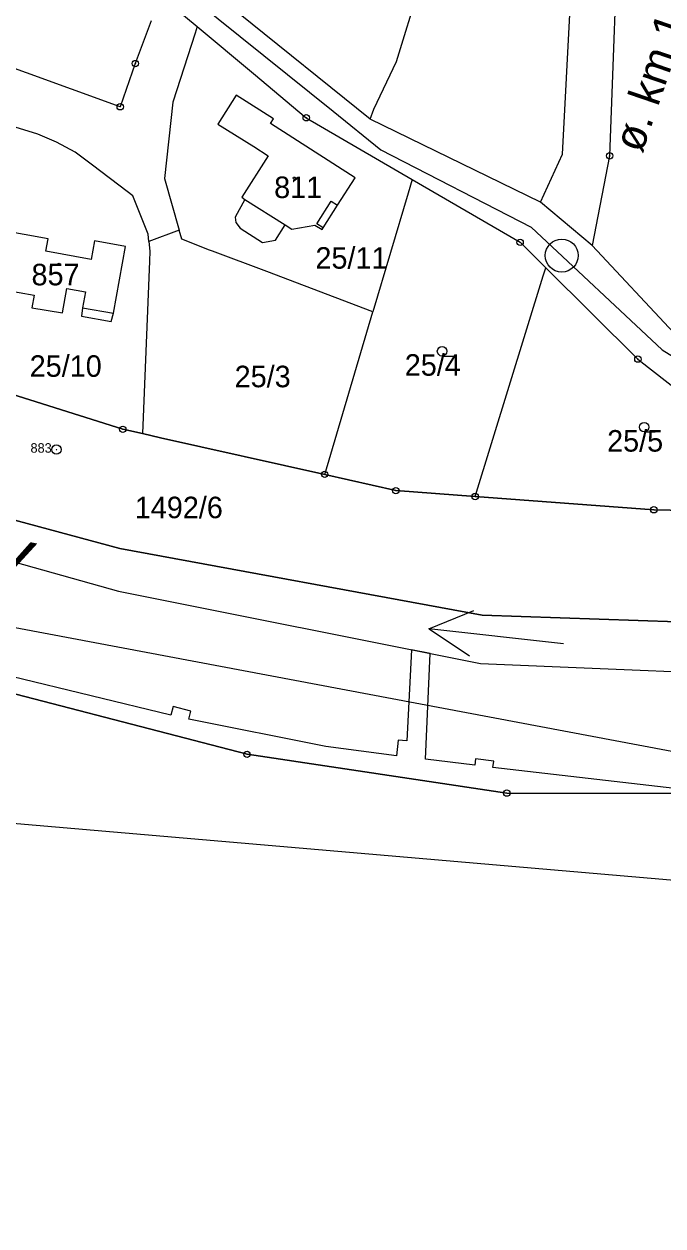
# Model space of a CAD drawing. Extents: x -537341 to -532984, y -1143469 to -1141314.
# Drawn here: x -533883.6 to -533782.7, y -1143459.1 to -1143269.2 of the extents above; entities that cross this region are included whole.
import ezdxf

# ---------------------------------------------------------------- set-up
doc = ezdxf.new("R2010")
doc.units = 0
for name, color, linetype in [('Hranice parcel', 7, 'Continuous'), ('parcelní_č_2000', 7, 'Continuous'), ('U_KM', 7, 'Continuous'), ('u_km_popis', 7, 'Continuous'), ('u_nadpis', 7, 'Continuous'), ('u_obec_Horní_Moš', 7, 'Continuous'), ('u_osa_stávající', 7, 'Continuous'), ('u_popis', 7, 'Continuous'), ('u_povodí', 7, 'Continuous'), ('Vnitřní kresba', 7, 'Continuous'), ('Věcná břemena k části', 7, 'Continuous'), ('x_formát_rám', 7, 'Continuous'), ('Značky bodu BP', 7, 'Continuous'), ('Značky budov', 7, 'Continuous'), ('Značky kultur', 7, 'Continuous')]:
    doc.layers.add(name, color=color, linetype=linetype)

# ---------------------------------------------------------------- blocks, each defined once
blk = doc.blocks.new('BIG')
at = {"layer": 'x_formát_rám'}
blk.add_line((0, 0), (-2100, 0), dxfattribs=at)

msp = doc.modelspace()

# ---------------------------------------------------------------- linework, layer by layer
at = {"layer": 'Hranice parcel'}
for p, q in [((-533862.31, -1143264.57), (-533856.28, -1143269.61)), ((-533828.95, -1143284.25), (-533849.76, -1143267.52)), ((-533802.08, -1143297.35), (-533828.95, -1143284.25)), ((-533793.92, -1143304.2), (-533802.08, -1143297.35)), ((-533859.12, -1143301.8), (-533863.9, -1143303.57)), ((-533781.01, -1143318), (-533793.92, -1143304.2)), ((-533836.14, -1143340.37), (-533828.52, -1143314.67))]:
    msp.add_line(p, q, dxfattribs=at)
for points in [[(-533785.04, -1143125.67), (-533791.14, -1143290.05), (-533793.92, -1143304.2)], [(-533828.95, -1143284.25), (-533828.36, -1143282.65), (-533824.78, -1143275.15), (-533821.19, -1143263.28), (-533817.82, -1143250.63), (-533816.72, -1143245.43), (-533815.35, -1143235.1), (-533814.52, -1143216.93), (-533815.7, -1143194.22), (-533815.75, -1143181.63), (-533815.27, -1143169.55)], [(-533802.08, -1143297.35), (-533798.61, -1143289.77), (-533794.82, -1143217.51), (-533793.35, -1143185), (-533793.03, -1143178.1), (-533793.07, -1143172.13)], [(-533863.56, -1143268.71), (-533866.06, -1143275.46), (-533868.45, -1143282.29), (-533905.8, -1143268.78)], [(-533856.28, -1143269.61), (-533856.63, -1143270.68), (-533860.15, -1143281.57), (-533861.44, -1143293.6), (-533859.12, -1143301.8)], [(-533856.28, -1143269.61), (-533847.4, -1143277.05), (-533839.06, -1143284.03), (-533822.32, -1143293.76)], [(-533853, -1143285.04), (-533847.34, -1143288.55), (-533845.07, -1143290.02), (-533849.26, -1143296.56), (-533848.74, -1143296.94), (-533850.31, -1143299.73), (-533850.18, -1143300.56), (-533849.48, -1143301.48), (-533845.96, -1143303.74), (-533843.91, -1143303.39), (-533842.37, -1143300.96), (-533841.35, -1143301.62), (-533837.69, -1143300.99), (-533836.55, -1143301.7), (-533836.38, -1143301.41), (-533834.1, -1143297.85), (-533831.35, -1143293.52), (-533844.73, -1143284.94), (-533844.22, -1143284.22), (-533850.14, -1143280.47), (-533853, -1143285.04)], [(-533863.9, -1143303.57), (-533864.01, -1143302.42), (-533866.44, -1143296.36), (-533867.33, -1143295.68), (-533872.81, -1143291.53), (-533875.55, -1143289.45), (-533878.53, -1143287.86), (-533881.44, -1143286.63), (-533887.8, -1143284.68)], [(-533822.32, -1143293.76), (-533822.97, -1143295.95), (-533828.52, -1143314.67)], [(-533822.32, -1143293.76), (-533805.28, -1143303.7), (-533801.24, -1143307.71)], [(-533635.65, -1143320.18), (-533621.98, -1143333.2), (-533669.13, -1143344.24), (-533673.43, -1143345.3), (-533684.54, -1143348.05), (-533705.36, -1143354.2), (-533711.3, -1143360.94), (-533727.16, -1143363.51), (-533755.86, -1143364.49), (-533811.29, -1143362.59), (-533868.5, -1143352.06), (-533907.21, -1143341.67), (-533958.4, -1143321.33), (-533977.94, -1143313.89), (-533996.94, -1143308.99), (-534032.19, -1143303.36), (-534039.92, -1143302.81)], [(-533882.39, -1143314.08), (-533877.55, -1143314.85), (-533876.87, -1143310.99), (-533873.95, -1143311.52), (-533874.41, -1143314.05), (-533874.56, -1143315.37), (-533869.86, -1143316.19), (-533869.51, -1143314.89), (-533867.62, -1143304.34), (-533872.5, -1143303.48), (-533873.01, -1143306.4), (-533880.19, -1143305.09), (-533879.84, -1143303.16), (-533887.46, -1143301.77), (-533889.21, -1143310.78), (-533882.03, -1143312.06), (-533882.39, -1143314.08)], [(-533828.52, -1143314.67), (-533845.29, -1143308.34), (-533853.85, -1143305.12), (-533854.32, -1143304.93), (-533858.73, -1143303.19), (-533859.12, -1143301.8)], [(-533863.9, -1143303.57), (-533863.77, -1143305.1), (-533863.83, -1143306.69), (-533864.93, -1143333.93)], [(-533812.37, -1143343.86), (-533801.63, -1143308.99), (-533801.24, -1143307.71)], [(-533801.24, -1143307.71), (-533786.68, -1143322.16), (-533777.13, -1143329.62), (-533764.51, -1143333.99)], [(-534038.97, -1143310.06), (-534031.18, -1143311.01), (-533998.92, -1143316.01), (-533979.87, -1143320.72), (-533960.35, -1143327.43), (-533909.08, -1143347.5), (-533868.71, -1143358.81), (-533811.53, -1143370.24), (-533756.11, -1143372.54), (-533679.67, -1143371.28), (-533668.56, -1143368.57), (-533664.28, -1143367.52), (-533654.7, -1143361.35), (-533580.69, -1143335.71), (-533556.9, -1143328.13)], [(-533895.36, -1143324.61), (-533889.64, -1143326.42), (-533868.04, -1143333.24), (-533864.93, -1143333.93)], [(-533864.93, -1143333.93), (-533862.1, -1143334.57), (-533836.14, -1143340.37)], [(-533836.14, -1143340.37), (-533824.92, -1143342.93), (-533812.37, -1143343.86)], [(-533812.37, -1143343.86), (-533784.16, -1143345.96), (-533765.98, -1143346.34)], [(-533755.18, -1143390.81), (-533807.39, -1143390.72), (-533848.41, -1143384.59), (-533897.59, -1143371.84), (-533928.82, -1143360.36), (-533960.85, -1143348.22)]]:
    msp.add_lwpolyline(points, dxfattribs=at)
at = {"layer": 'U_KM'}
msp.add_circle((-533798.71, -1143305.8), 2.6, dxfattribs=at)
at = {"layer": 'u_nadpis'}
msp.add_lwpolyline([(-535757.21, -1143234.5), (-535708.7, -1143186.18), (-535532.3, -1143063.53), (-535234.92, -1142978.15), (-534703.86, -1143121.98), (-534494.71, -1143163.58), (-534139.73, -1143316.61), (-533671.97, -1143404.67)], dxfattribs=at)
at = {"layer": 'u_obec_Horní_Moš'}
for p, q in [((-533862.31, -1143264.57), (-533856.28, -1143269.61)), ((-533828.95, -1143284.25), (-533849.76, -1143267.52)), ((-533802.08, -1143297.35), (-533828.95, -1143284.25)), ((-533793.92, -1143304.2), (-533802.08, -1143297.35)), ((-533781.01, -1143318), (-533793.92, -1143304.2))]:
    msp.add_line(p, q, dxfattribs=at)
for points in [[(-533856.28, -1143269.61), (-533847.4, -1143277.05), (-533839.06, -1143284.03), (-533822.32, -1143293.76)], [(-533822.32, -1143293.76), (-533805.28, -1143303.7), (-533801.24, -1143307.71)], [(-533801.24, -1143307.71), (-533786.68, -1143322.16), (-533777.13, -1143329.62), (-533764.51, -1143333.99)]]:
    msp.add_lwpolyline(points, dxfattribs=at)
at = {"layer": 'u_osa_stávající'}
msp.add_lwpolyline([(-534029.94, -1143093), (-534024.36, -1143095.75), (-534018.54, -1143098.11), (-534002.63, -1143106.06), (-533979.52, -1143113.76), (-533965.65, -1143121.26), (-533942.32, -1143139.25), (-533937.74, -1143147.06), (-533937.26, -1143155.21), (-533938.57, -1143165.94), (-533939.01, -1143180.16), (-533935.95, -1143193.33), (-533920.3, -1143207.37), (-533896.4, -1143226.73), (-533870.02, -1143249.8), (-533856.71, -1143265.33), (-533834.82, -1143282.99), (-533827.26, -1143289.09), (-533803.51, -1143301.3), (-533782.84, -1143320.67), (-533772.42, -1143327.12)], dxfattribs=at)
at = {"layer": 'u_popis'}
for p, q in [((-533819.72, -1143364.75), (-533812.6, -1143361.85)), ((-533798.45, -1143367.15), (-533819.72, -1143364.75)), ((-533819.66, -1143364.77), (-533813.28, -1143369.03))]:
    msp.add_line(p, q, dxfattribs=at)
at = {"layer": 'u_povodí'}
for p, q in [((-533868.5, -1143352.06), (-533907.21, -1143341.67)), ((-533811.29, -1143362.59), (-533868.5, -1143352.06))]:
    msp.add_line(p, q, dxfattribs=at)
for points in [[(-534032.19, -1143303.36), (-533996.94, -1143308.99), (-533977.94, -1143313.89), (-533958.4, -1143321.33), (-533907.21, -1143341.67), (-533868.5, -1143352.06), (-533811.29, -1143362.59), (-533755.86, -1143364.49), (-533727.16, -1143363.51), (-533711.3, -1143360.94), (-533705.36, -1143354.2), (-533684.54, -1143348.05), (-533673.43, -1143345.3), (-533669.13, -1143344.24), (-533621.98, -1143333.2), (-533635.65, -1143320.18)], [(-534031.18, -1143311.01), (-533998.92, -1143316.01), (-533979.87, -1143320.72), (-533960.35, -1143327.43), (-533909.08, -1143347.5), (-533868.71, -1143358.81), (-533811.53, -1143370.24), (-533756.11, -1143372.54), (-533679.67, -1143371.28), (-533668.56, -1143368.57), (-533664.28, -1143367.52), (-533654.7, -1143361.35), (-533580.69, -1143335.71), (-533556.9, -1143328.13)], [(-533864.93, -1143333.93), (-533868.04, -1143333.24), (-533889.64, -1143326.42), (-533895.36, -1143324.61)], [(-533836.14, -1143340.37), (-533862.1, -1143334.57), (-533864.93, -1143333.93)], [(-533812.37, -1143343.86), (-533824.92, -1143342.93), (-533836.14, -1143340.37)], [(-533765.98, -1143346.34), (-533784.16, -1143345.96), (-533812.37, -1143343.86)], [(-533727.16, -1143363.51), (-533755.86, -1143364.49), (-533811.29, -1143362.59)]]:
    msp.add_lwpolyline(points, dxfattribs=at)
at = {"layer": 'Vnitřní kresba'}
for p, q in [((-533848.74, -1143296.94), (-533842.37, -1143300.96)), ((-533837.4, -1143300.77), (-533835.11, -1143297.2)), ((-533835.11, -1143297.2), (-533834.1, -1143297.85)), ((-533836.38, -1143301.41), (-533837.4, -1143300.77)), ((-533874.41, -1143314.05), (-533869.51, -1143314.89))]:
    msp.add_line(p, q, dxfattribs=at)
at = {"layer": 'Věcná břemena k části'}
for points in [[(-533776.74, -1143390.45), (-533809.59, -1143386.66), (-533809.44, -1143385.69), (-533812.32, -1143385.28), (-533812.45, -1143386.29), (-533820.23, -1143385.37), (-533819.5, -1143368.65), (-533822.46, -1143368.06), (-533823.16, -1143382.45), (-533824.52, -1143382.35), (-533824.8, -1143384.82), (-533835.98, -1143383.37), (-533857.61, -1143379.01), (-533857.29, -1143377.77), (-533860.09, -1143377.02), (-533860.46, -1143378.43), (-533885.64, -1143372.3)], [(-533897.59, -1143371.84), (-533848.41, -1143384.59), (-533807.39, -1143390.72), (-533775.54, -1143390.77)]]:
    msp.add_lwpolyline(points, dxfattribs=at)
at = {"layer": 'Značky bodu BP'}
for centre, radius in [((-533866.06, -1143275.46), 0.5), ((-533866.06, -1143275.46), 0.0303), ((-533868.45, -1143282.29), 0.5), ((-533868.45, -1143282.29), 0.0303), ((-533839.06, -1143284.03), 0.5), ((-533839.06, -1143284.03), 0.0303), ((-533791.14, -1143290.05), 0.5), ((-533791.14, -1143290.05), 0.0303), ((-533805.28, -1143303.7), 0.5), ((-533805.28, -1143303.7), 0.0303), ((-533786.68, -1143322.16), 0.5), ((-533786.68, -1143322.16), 0.0303), ((-533868.04, -1143333.24), 0.5), ((-533868.04, -1143333.24), 0.0303), ((-533878.51, -1143336.44), 0.75), ((-533878.51, -1143336.44), 0.03), ((-533836.14, -1143340.37), 0.5), ((-533836.14, -1143340.37), 0.0303), ((-533824.92, -1143342.93), 0.5), ((-533824.92, -1143342.93), 0.0303), ((-533812.37, -1143343.86), 0.5), ((-533812.37, -1143343.86), 0.0303), ((-533784.16, -1143345.96), 0.5), ((-533784.16, -1143345.96), 0.0303), ((-533848.41, -1143384.59), 0.5), ((-533848.41, -1143384.59), 0.0303), ((-533807.39, -1143390.72), 0.5), ((-533807.39, -1143390.72), 0.0303)]:
    msp.add_circle(centre, radius, dxfattribs=at)
at = {"layer": 'Značky budov'}
for centre in [(-533840.93, -1143293.56), (-533878.1, -1143307.16)]:
    msp.add_circle(centre, 0.175, dxfattribs=at)
at = {"layer": 'Značky kultur'}
for p, q in [((-533817.61, -1143321.67), (-533815.86, -1143321.67)), ((-533785.69, -1143333.65), (-533783.94, -1143333.65))]:
    msp.add_line(p, q, dxfattribs=at)
for centre in [(-533817.61, -1143320.92), (-533785.69, -1143332.9)]:
    msp.add_circle(centre, 0.75, dxfattribs=at)

# ---------------------------------------------------------------- block references
at = {"layer": 'u_povodí', "xscale": 2.0000000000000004, "yscale": 1.9999999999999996, "rotation": -4.9171773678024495}
msp.add_blockref('BIG', (-533146.62, -1143459.1), dxfattribs=at)

# ---------------------------------------------------------------- texts
at = {"layer": 'parcelní_č_2000'}
for s, p in [('811', (-533844.13, -1143296.71)), ('25/11', (-533837.61, -1143307.87)), ('857', (-533882.45, -1143310.5)), ('25/10', (-533882.74, -1143324.95)), ('25/4', (-533823.5, -1143324.78)), ('25/3', (-533850.37, -1143326.6)), ('25/5', (-533791.54, -1143336.77)), ('1492/6', (-533866.14, -1143347.29))]:
    msp.add_text(s, height=3.4, dxfattribs=at).set_placement(p)
at = {"layer": 'u_km_popis'}
msp.add_text('ø. km 11,500', height=5, rotation=71.1043, dxfattribs=at).set_placement((-533786.04, -1143289.77))
at = {"layer": 'u_nadpis'}
msp.add_text(' ø. km. 11,165 - 11,500 - ÚSEK BEZ ÚPRAVY', height=8, rotation=348.6941, dxfattribs=at).set_placement((-534098.59, -1143316.06))
at = {"layer": 'Značky bodu BP'}
msp.add_text('883', height=1.5, dxfattribs=at).set_placement((-533882.61, -1143336.94))

doc.saveas('drawing.dxf')
